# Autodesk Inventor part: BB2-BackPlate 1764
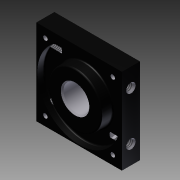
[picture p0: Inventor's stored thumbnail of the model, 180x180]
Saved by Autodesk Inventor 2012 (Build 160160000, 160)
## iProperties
Company: FirstCadLibrary
Shininess: 64.0
Length Units: 11269
Angle Units: 11279
Time Units: 11290
Mass Units: 11283
Length Display Precision: 3
Angle Display Precision: 2
Compacted: True
Part Number: BB2-BackPlate 1764
Document SubType Name: Modeling
Created: 2007-01
Designer: Ed Sparks
Material: Aluminum-6061-AHC
Catalog Web Link: www.banebots.com
Vendor: BaneBots
Mass: 139.924 g
Surface Area: 166.185 cm^2
Volume: 51.6326 cm^3
Density: 2.71 g/cm^3
Density: 0.0
Volumn: 0.0
Area: 0.0
PropertySet Name: Model Information
Control State: 0
Master: False
Checked Out: False
Author: Ed Sparks
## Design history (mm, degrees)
sketch "Sketch1"
  geometry: L1 (-31.75, 31.75)-(31.75, 31.75); L2 (31.75, 31.75)-(31.75, -31.75); L3 (31.75, -31.75)-(-31.75, -31.75); L4 (-31.75, -31.75)-(-31.75, 31.75); L5 (0, 0)-(0, 31.75); L6 (0, 0)-(0, -31.75); L7 (0, 0)-(31.75, 0); L8 (0, 0)-(-31.75, 0)
  constraints: 16 end point, 4 midpoint, 2 collinear, 2 parallel, 1 horizontal, 1 perpendicular, 1 other
  dimensions: "d0" = 63.5 distance of L1.end L2.end; "d1" = 63.5 distance of L1.start L1.end
extrude "Extrusion1" new body sketch "Sketch1" stored distance "d2" = 13.4; taper "d3" = 0 deg
sketch "Sketch2"
  geometry: C1 r 31 at (0, 0)
  constraints: 1 centre point
  dimensions: "d4" = 62 diameter of C1
extrude "Extrusion2" cut sketch "Sketch2" distance "d5" = 5; taper "d6" = 0 deg
sketch "Sketch3"
  geometry: C1 r 20 at (-0.807, 0)
  constraints: 1 centre point
  dimensions: "d7" = 40 diameter of C1
extrude "Extrusion3" join sketch "Sketch3" distance "d8" = 8; taper "d9" = 0 deg
fillet "Fillet1" dims "d10" = 1
sketch "Sketch6"
  geometry: C1 r 25 at (0, 0)
  constraints: 1 centre point
  dimensions: "d13" = 50 diameter of C1
extrude "Extrusion4" join sketch "Sketch6" distance "d14" = 6; taper "d15" = 0 deg
sketch "Sketch7"
  geometry: C1 r 25 at (0, 0) reference; 1 further point
  dimensions: "d16" = 25 horizontal distance of point (-25, 25) C1.centre; "d17" = 25 horizontal distance of C1.centre point (-25, 25)
hole "Hole1" sketch "Sketch7" at (-25, 25) diameter "d18" = 3.2; stored, may be unused: countersink angle "d22" = 82 deg, drill point angle "d24" = 118 deg; dims "d19" = 6, "d20" = 6.3, "d21" = 10.3, "d23" = 8
pattern_circular "Circular Pattern1" dims angle "d27" = 360 deg
sketch "Sketch8"
  geometry: C1 r 25 at (0, 0) reference; 1 further point
  constraints: 1 coincident
hole "Hole2" sketch "Sketch8" at (0, 0) diameter "d28" = 19.2; stored, may be unused: countersink angle "d32" = 82 deg, drill point angle "d34" = 118 deg; dims "d29" = 6, "d30" = 6.3, "d31" = 10.3, "d33" = 8
chamfer "Chamfer1" distance "d35" = 1; stored, may be unused: second distance "d36" = 2, angle "d59" = 45 deg
sketch "Sketch9"
  geometry: L1 (63.5, 0)-(0, 0) reference; L2 (0, 0)-(0, -13.4) reference; L3 (0, -13.4)-(63.5, -13.4) reference; L4 (63.5, 0)-(63.5, -13.4) reference; L5 (0, -6.7)-(63.5, -6.7); L6 (31.75, 0)-(31.75, -13.4); 1 further point
  constraints: 4 end point, 4 midpoint, 1 point on line
  dimensions: "d37" = 18 distance from line of point (13.75, -6.7) L6
hole "Hole3" sketch "Sketch9" at (13.75, -6.7) diameter "d38" = 4.978; stored, may be unused: countersink angle "d42" = 82 deg, drill point angle "d44" = 118 deg; dims "d39" = 12, "d40" = 6.3, "d41" = 10.3, "d43" = 13.7
mirror "Mirror1"
mirror "Mirror2"
chamfer "Chamfer2" distance "d45" = 1; stored, may be unused: second distance "d46" = 2, angle "d60" = 45 deg
workplane "Work Plane1"
sketch "Sketch10"
  geometry: L1 (-31.75, -6.7)-(31.75, -6.7) reference; L2 (0, -6.7)-(0, -22.916); 1 further point
  constraints: 2 end point, 1 midpoint, 1 perpendicular, 1 point on line
  dimensions: "d48" = 3.5 distance from line of point (0, -10.2) L1
hole "Hole4" sketch "Sketch10" at (0, -10.2) diameter "d49" = 2.459; stored, may be unused: countersink angle "d53" = 82 deg, drill point angle "d55" = 118 deg; dims "d50" = 6, "d51" = 6.3, "d52" = 10.3, "d54" = 7.5
pattern_circular "Circular Pattern2" dims angle "d58" = 360 deg
body "Solid1"
other parameters: "d47" = 25
